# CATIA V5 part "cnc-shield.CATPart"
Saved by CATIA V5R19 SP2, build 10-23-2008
Part number: CNC-SHIELD
Revision: 1
Definition: design
Nomenclature: CNC-SHIELD
Source: made
Description: NOT SPECIFIED
Bounding box of the stored display mesh (mm): x 0 to 52.96, y 0 to 19.8, z 0 to 68.19
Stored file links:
  Z:\fausse table rondelle-20220905T211342Z-001\fausse table rondelle\cnc-shield.CATPart
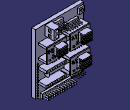
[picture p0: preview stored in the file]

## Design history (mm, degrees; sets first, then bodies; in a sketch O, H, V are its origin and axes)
AxisSystem1: origin (0, 0, 0), X (1, 0, 0), Y (0, 1, 0), Z (0, 0, 1)
Body1 "MANIFOLD_SOLID_BREP #21932" (main body)
  Solid1: solid without history
Body2 "MANIFOLD_SOLID_BREP #22020"
  Solid2: solid without history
